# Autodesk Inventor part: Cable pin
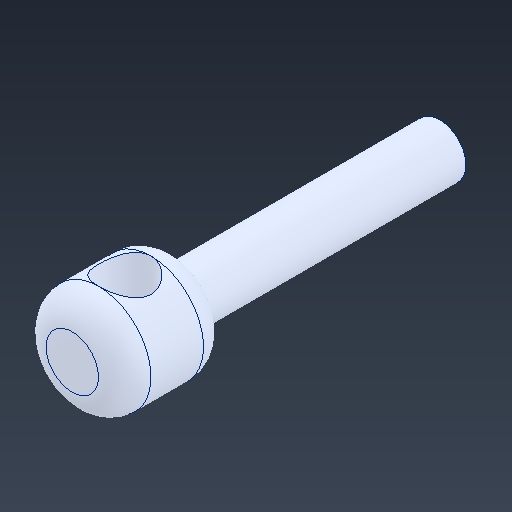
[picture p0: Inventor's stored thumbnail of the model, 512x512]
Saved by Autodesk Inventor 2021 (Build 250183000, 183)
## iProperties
Created: 2020-02
Part Number: Cable pin
Material: SOLIDWORKS Materials|6061 Alloy
Document SubType Name: Modeling
Designer: ftrauzettel
Density: 2.7 g/cm^3
Appearance: 221,232,255
Author: ftrauzettel
Sending System: SolidWorks 2016
Last Author: Pam
Last Saved: 2020-02-20
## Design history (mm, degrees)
feature "Cut-Extrude1"
body "Solid1"
